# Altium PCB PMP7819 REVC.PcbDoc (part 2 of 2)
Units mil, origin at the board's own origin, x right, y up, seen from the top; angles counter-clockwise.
Board outline 2280 x 1450 mil, 4 copper layers (Top Layer, Mid-Layer 1, Mid-Layer 2, Bottom Layer), stack 62.2 mil thick; 94 components, 42 nets, 265 pads, 199 vias.
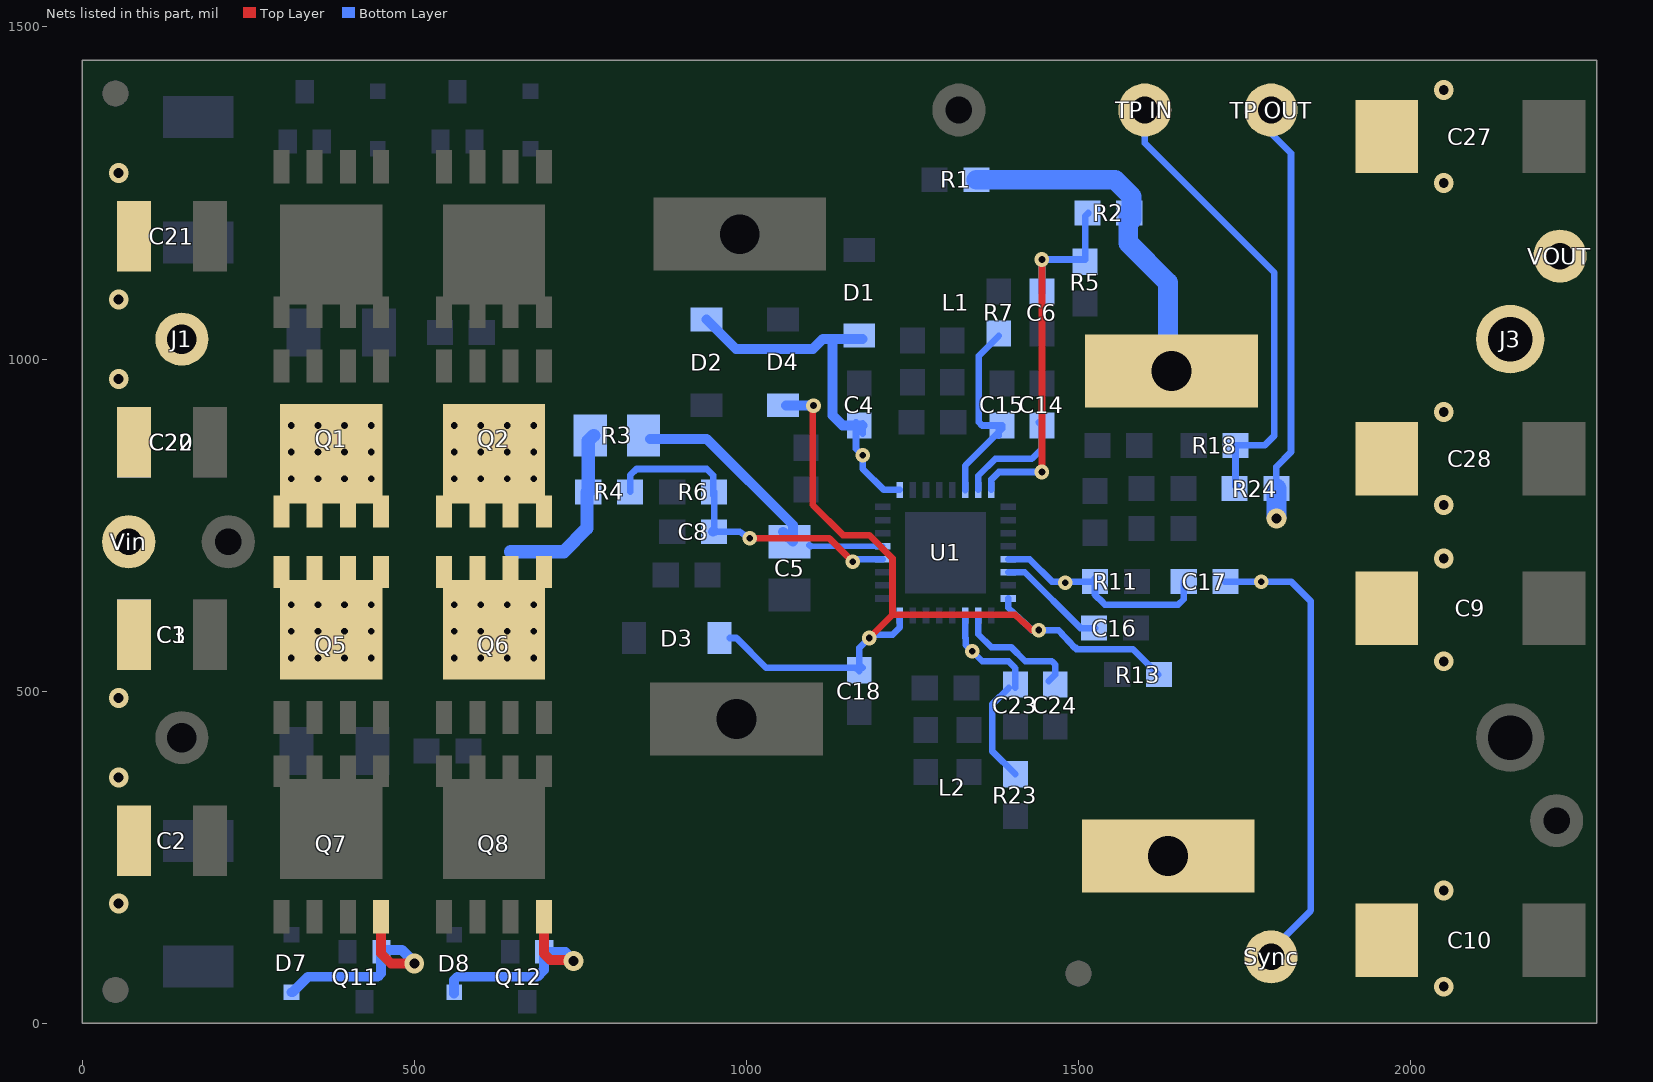
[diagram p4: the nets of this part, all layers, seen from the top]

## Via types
v1: diameter 28, hole 10, Top Layer to Bottom Layer, tented top, 96 vias
v2: diameter 30, hole 15, Top Layer to Bottom Layer, 80 vias
v3: diameter 22, hole 10, Top Layer to Bottom Layer, 23 vias

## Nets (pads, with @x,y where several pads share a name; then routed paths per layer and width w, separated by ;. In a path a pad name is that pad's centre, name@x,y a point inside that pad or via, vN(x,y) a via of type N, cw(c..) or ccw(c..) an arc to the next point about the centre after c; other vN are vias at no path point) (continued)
NetD7_1: D7.1 Q7.4 Q11.2 | length 366.5
  Top Layer w15: Q7.4@450,160 450,105 465,90 v2(500,90)
  Bottom Layer w15: D7.1@315,46.69 316.69,46.69 340,70 445,70 450,75 450,110 481.87,110 500,91.87 v2(500,90) v2@490,100
NetD8_1: D8.1 Q8.4 Q12.2 | length 344.9
  Top Layer w15: Q8.4@695,165 Q8.4@695,160.5 695,105 705,95 v2@740,95
  Bottom Layer w15: D8.1@560,45 D8.1@560,46.69 560,65 565,70 685,70 695,80 Q12.2@695,105 ; Q12.2@695.59,107.4 727.6,107.4 v2@740,95
  other v2: 740,94
NetR18_2: "TP IN.1" R18.2 R24.1 | length 692.5
  Bottom Layer w10: 1600,1340 1600,1325 1795,1130 1795,885 1780,870 R18.2@1736.5,870 ; R24.1@1740,805 1736.5,808.5 R18.2@1736.5,870 ; 1762.01,870 R18.2@1736.5,870
RAMP1: C15.1 R7.1 U1.6 | length 315.4
  Bottom Layer w10: U1.6@1329.53,802.93 1329.53,839.53 1352.67,862.67 1385,895 C15.1@1385,900 1355,900 1350,905 1350,915 ; 1350,914.18 1350,1005 R7.1@1380,1035 ; C15.1@1380,885 C15.1@1380,900
RAMP2: C23.1 R23.1 U1.19 | length 318.4
  Bottom Layer w9.84: U1.19@1329.53,613.95 1329.53,580.47 1330,580 1330,570 v3(1340,560) 1355,545 1394.77,545 1405,534.77 C23.1@1405,505
  Bottom Layer w10: C23.1@1395,505 1370,480 1370,410 R23.1@1405,375
RES: C16.1 U1.14 | length 165.3
  Bottom Layer w9.84: U1.14@1394.49,678.91 1419.01,678.91 1502.92,595 C16.1@1525,595
RT: C17.2 R11.2 U1.13 | length 358.3
  Bottom Layer w9.84: 1411.17,698.6 U1.13@1394.49,698.6 1426.4,698.6 1460,665 R11.2@1525,665
  Bottom Layer w10: R11.2@1525,670 1525,645 1536.7,633.3 ; 1535,635 1540,630 1650,630 1658.5,638.5 C17.2@1658.5,665
  other v3: 1480,663
SS1: C14.1 U1.7 | length 176
  Bottom Layer w9.84: U1.7@1349.21,802.93 1349.21,824.21 1375,850 1430,850 1445,865 C14.1@1445,900 C14.1@1440,905
SS2: C24.1 U1.18 | length 192.1
  Bottom Layer w9.84: U1.18@1349.21,613.95 1349.21,585.79 1368.61,566.4 1398.61,566.4 1420,545 1460,545 1465,540 1465,525 C24.1@1455,515
SYNC: C17.1 Sync.1 | length 706.4
  Bottom Layer w10: C17.1@1720,665 v3(1775,665) 1820,665 1850,635 1850,170 Sync.1@1780,100
UVLO: C8.1 R4.1 R6.2 U1.28 | length 518.1
  Top Layer w10: v3(1005,730) 1125,730 v3(1160,695)
  Bottom Layer w9.84: v3(1160,695) 1163.6,698.6 U1.28@1205.51,698.6
  Bottom Layer w10: R4.1@825,800 825,825 834.6,834.6 940.4,834.6 950,825 R6.2@950,795 ; C8.1@951.5,741.5 R6.2@951.5,800 ; C8.1@955,740 990,740 v3(1005,730)
  Bottom Layer w15: C8.1@950,740 C8.1@951.5,741.5
VCC1: C4.1 D1.1 D2.2 U1.1 | length 584.9
  Bottom Layer w9.84: v3(1175,855) 1175,835 1207.07,802.93 U1.1@1231.1,802.93 ; C4.1@1175,887.5 C4.1@1175,903
  Bottom Layer w10: C4.1@1165,905 1165,865 v3(1175,855)
  Bottom Layer w15: D2.2@940,1059.47 984.47,1015 1100,1015 1115,1030 D1.1@1175,1030 ; 1130,1030 1130,915 1145,900 C4.1@1175,900
VCC2: C18.1 D3.2 D4.1 R13.1 U1.16 U1.24 | length 1331.1
  Top Layer w10: v3@1100,930 1100,780.46 1145.46,735 1185,735 1220,700 1220,615 ; v3(1185,580) 1220,615 ; v3(1440,592) 1430,592 1405,615 1220,615
  Bottom Layer w9.84: C18.1@1175,535 1170,540 1170,565 1180,575 1185,575 v3(1185,580) 1190,585 1220,585 1231.1,596.1 U1.24@1231.1,613.95 ; U1.16@1394.49,639.54 1394.49,625.51 1430,592 1470,592 1495,565 1496.84,565 1496.84,563.38 1581.62,563.38 R13.1@1620,525
  Bottom Layer w10: D3.2@975,580 985,580 1030,535 1165,535 C18.1@1170,530
  Bottom Layer w15: D4.1@1060,930 v3@1100,930
  other v3: 1101,930
VCCDIS: C6.1 R2.1 R5.1 U1.8 | length 603.6
  Top Layer w10: v3(1445,830) 1445,1050 v3(1445,1150)
  Bottom Layer w9.84: U1.8@1368.9,802.93 1368.9,818.67 1380.23,830 v3(1445,830)
  Bottom Layer w10: C6.1@1445,1100 v3(1445,1150) 1510,1150 1510,1215 R2.1@1515,1220
VIN: C1.1 C2.1 C3.1 C20.1 C21.1 C22.1 J1.1 Q1.5 Q1.6 Q1.7 Q1.8 Q1.9 Q2.5 Q2.6 Q2.7 Q2.8 Q2.9 Q5.5 Q5.6 Q5.7 Q5.8 Q5.9 Q6.5 Q6.6 Q6.7 Q6.8 Q6.9 R3.2 R4.2 Vin.1 | length 279.9
  Bottom Layer w20: 645,710 725,710 760,745 760,800 R4.2@765,805 ; R4.2@762.01,800 762.01,877.01 R3.2@770,885
  other v1: 315,550 355,550 395,550 435,550 560,550 600,550 640,550 680,550 315,590 355,590 395,590 435,590 560,590 600,590 640,590 680,590 315,630 355,630 395,630 435,630 560,630 600,630 640,630 680,630 315,820 355,820 395,820 435,820 560,820 600,820 640,820 680,820 315,860 355,860 395,860 435,860 560,860 600,860 640,860 680,860 315,900 355,900 395,900 435,900 560,900 600,900 640,900 680,900
  other v2: 55,180 55,370 55,490 55,970 55,1090 55,1280
"VIN U1": C5.1 R3.1 U1.29 | length 426.3
  Bottom Layer w8: 1096.72,718.28 U1.29@1205.51,718.28
  Bottom Layer w9.84: C5.1@1095,720 1096.72,718.28
  Bottom Layer w15: R3.1@855,880 940,880 1070,750 1070,725 C5.1@1055,740
VOUT1: "TP OUT.1" C9.1 C10.1 C27.1 C28.1 J3.1 L1.2 L2.2 R1.1 R2.2 R24.2 VOUT.1 | length 1138.2
  Bottom Layer w10: 1790,1340 1820,1310 1820,860 1797.99,837.99 R24.2@1797.99,805
  Bottom Layer w30: R1.1@1346.5,1270 1555,1270 1580,1245 R2.2@1580,1210 ; R2.2@1575,1220 1575,1175 1635,1115 L1.2@1635,985 ; v2@1797.99,762.01 R24.2@1797.99,805
  other v2: 2050,55 2050,200 2050,545 2050,700 1797.99,760 2050,780 2050,920 2050,1265 2050,1405
pads on no net: FID1.1 FID2.1 FID3.1 FID4.1 FID5.1 FID6.1 Q9.0 Q10.0 Q11.0 Q12.0

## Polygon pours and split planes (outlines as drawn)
CS2_P on Top Layer "Top Layer-CS2_P" (solid, remove dead copper, pour order 83): 120,190 415,190 415,70 530,70 530,190 660,190 660,70 805,70 805,5 120,5
CS1_P on Top Layer "Top Layer-CS1_P" (solid, remove dead copper, pour order 87): 120,1260 120,1450 750,1450 750,1260 580,1260 580,1385 465,1385 465,1260
GND on Top Layer "Top Layer-GND" (solid, remove dead copper, pour order 72): 765,1450 1140,1450 1140,1310 765,1310
HO2_N on Top Layer "Top Layer-HO2_N" (solid, remove dead copper, pour order 64): 745,355 690,355 690,215 745,215
HO2_N on Top Layer "Top Layer-HO2_N" (solid, remove dead copper, pour order 79): 285,485 415,485 415,421.19 530,421.19 530,485 660,485 660,421.19 710,421.19 710,215 285,215
VIN on Top Layer "Top Layer-VIN" (solid, remove dead copper, pour order 65): 285,935 720,935 720,515 285,515
HO1_N on Top Layer " Top Layer 1-HO1_N" (solid, remove dead copper, pour order 74): 270,1235 270,1045 335,1045 335,965 465,965 465,1045 575,1045 575,965 710,965 710,1235
GND on Top Layer "Top Layer-GND" (solid, remove dead copper, pour order 78): 740,1085 1115,1085 1115,520 740,520
GND on Top Layer "Top Layer-GND" (solid, remove dead copper, pour order 59): 750,0 750,130 1125,130 1125,0
VOUT1 on Top Layer "Top Layer-VOUT1" (solid, remove dead copper, pour order 73): 1165,1450 2075,1450 2075,1210 2300,1210 2300,975 2075,975 2075,5 1165,5
GND on Top Layer "Top Layer-GND" (solid, remove dead copper, pour order 60): 1235,770 1365,770 1365,645 1235,645
GND on Top Layer "Top Layer-GND" (solid, remove dead copper, pour order 84): 245,640 245,220 115,220 115,640
HO1_N on Top Layer "Top Layer-HO1_N" (solid, remove dead copper, pour order 89): 670,1275 1115,1275 1115,1095 670,1095
GND on Top Layer "Top Layer-GND" (solid, remove dead copper, pour order 61): 2300,960 2105,960 2105,0 2300,0
GND on Top Layer "Top Layer-GND" (solid, remove dead copper, pour order 62): 2300,1450 2300,1215 2295,1220 2105,1220 2105,1450
HO2_N on Top Layer "Top Layer 1-HO2_N" (solid, remove dead copper, pour order 63): 730,150 1115,150 1115,515 855,515 855,355 730,355
VIN on Top Layer "Top Layer-VIN" (solid, remove dead copper, pour order 66): 110,1450 110,0 0,0 0,1450
GND on Top Layer "Top Layer-GND" (solid, remove dead copper, pour order 80): 115,1295 245,1295 245,625 115,625
HO1_N on Bottom Layer "Bottom Layer-HO1_N" (solid, remove dead copper, pour order 71): 1115,1225 300,1225 300,1105 1115,1105
VOUT1 on Bottom Layer "Bottom Layer-VOUT1" (solid, remove dead copper, pour order 98): 2080,1450 1510,1450 1510,0 2080,0
GND on Bottom Layer "Bottom Layer-GND" (solid, remove dead copper, pour order 55): 1560,615 1690,615 1690,415 1390,415 1390,475 1495,475 1495,500 1640,500 1640,555 1630,565 1560,565
GND on Bottom Layer "Bottom Layer 2-GND" (solid, remove dead copper, pour order 56): 1410,735 1445,735 1455,725 1695,725 1695,690 1445,690 1445,695 1430,710 1410,710
GND on Bottom Layer "Bottom Layer-GND" (solid, remove dead copper, pour order 69): 1545,1125 1465,1125 1465,1075 1410,1075 1410,1015 1360,1015 1360,925 1470,925 1470,840 1560,840 1560,925 1515,925 1515,1040 1545,1040
GND on Bottom Layer "Bottom Layer-GND" (solid, remove dead copper, pour order 94): 2300,1450 2105,1450 2105,0 2300,0
GND on Bottom Layer "Bottom Layer-GND" (solid, remove dead copper, pour order 57): 120,1215 250,1215 245,1210 245,240 120,240
CS2_P on Bottom Layer "Bottom Layer-CS2_P" (solid, remove dead copper, pour order 70): 120,90 120,0 725,0 725,90
CS1_P on Bottom Layer "Bottom Layer-CS1_P" (solid, remove dead copper, pour order 58): 715,1360 715,1430 120,1430 120,1360
VIN on Bottom Layer "Bottom Layer-VIN" (solid, remove dead copper, pour order 92): 110,0 110,1450 0,1450 0,0
GND on Bottom Layer "Bottom Layer-GND" (solid, remove dead copper, pour order 86): 780,145 1560,145 1560,0 780,0
GND on Bottom Layer "Bottom Layer-GND" (solid, remove dead copper, pour order 88): 745,1450 1405,1450 1405,1335 745,1335
VIN on Bottom Layer "Bottom Layer-VIN" (solid, remove dead copper, pour order 77): 790,920 790,515 270,515 270,920
HO2_N on Bottom Layer "Bottom Layer-No Net" (solid, remove dead copper, pour order 82): 850,515 1115,515 1115,235 290,235 290,350 850,350
VOUT1 on Mid-Layer 1 "Mid-Layer 1-VOUT1" (solid, remove dead copper, pour order 76): 2300,1450 2300,0 1505,0 1505,1450
GND on Mid-Layer 1 "Mid-Layer 1-GND" (solid, remove dead copper, pour order 90): 745,0 1490,0 1490,600 745,600
GND on Mid-Layer 1 "Mid-Layer 1-GND" (solid, remove dead copper, pour order 91): 745,1450 745,500 1495,500 1495,1450
GND on Mid-Layer 1 "Mid-Layer 1-GND" (solid, remove dead copper, pour order 96): 235,510 130,510 130,340 235,340
VIN on Mid-Layer 1 "Mid-Layer 1-VIN" (solid, remove dead copper, pour order 68): 0,1450 730,1450 730,5 0,5
VIN on Mid-Layer 2 "Mid-Layer 2-VIN" (solid, remove dead copper, pour order 85): 5,1445 105,1445 105,0 5,0
GND on Mid-Layer 2 "Mid-Layer 2-GND" (solid, remove dead copper, pour order 97): 10,0 2285,0 2285,1450 10,1450

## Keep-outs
Keep-Out Layer:
  lines w9.87: 0,0 0,1450
  lines w10: 0,0 2300,0 2300,1450 0,1450
  text ".Layer_Name" at -1288,-5172.49 h60
  text "880" at 1252.5,-5172.49 h60

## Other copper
Top Layer:
  rectangle net CS2_P: 723,21 800,65
  rectangle net VIN: 100,990 150,1070
  text ".Layer_Name" at -1288,-5172.49 h60
  text "880" at 1252.5,-5172.49 h60
Mid-Layer 1:
  rectangle net HO1_N: 295,1105 695,1215
  rectangle net HO2_N: 295,235 695,345
  rectangle net CS1_P: 115,1385 760,1435
  rectangle net CS2_P: 110,20 800,65
Mid-Layer 2:
  rectangle net VIN: 70,990 150,1070
  rectangle net HO1_N: 295,1100 455,1220
  rectangle net HO1_N: 540,1100 700,1220
  rectangle net VIN: 300,530 455,650
  rectangle net VIN: 295,800 455,920
  rectangle net VIN: 540,800 700,920
  rectangle net VIN: 540,530 700,650
  rectangle net HO2_N: 300,230 455,350
  rectangle net HO2_N: 540,230 700,350
  rectangle net CS1_P: 120,1385 760,1435
  rectangle net CS2_P: 110,20 800,65
Bottom Layer:
  rectangle net VIN: 95,990 150,1070
  text ".Layer_Name" at -1288,-5172.49 h60
  text "880" at 1252.5,-5172.49 h60

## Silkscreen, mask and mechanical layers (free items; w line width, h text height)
Top Overlay:
  text "VIN" at 45,1000 h25 r90
  text "GND" at 45,400 h25 r90
  text ".Layer_Name" at -1288,-5172.49 h60
  text "880" at 1252.5,-5172.49 h60
Bottom Overlay:
  circle w10: c1095,314 r55
  text ".Pcb_File_Name_No_Path" at 1935,315 h35 r270
  text ".CopyrightYear" at 935,300 h35
  text "TI" at 1015,300 h35
  text "C" at 1105,300 h35
  text "UL94V-0" at 1020,225 h35
  text "MADE IN U.S." at 1300,30 h35
  text ".Layer_Name" at -1288,-5172.49 h60
  text "880" at 1252.5,-5172.49 h60
Top Paste:
  text ".Layer_Name" at -1288,-5172.49 h60
  text "881" at 1252.5,-5172.49 h60
Bottom Paste:
  text ".Layer_Name" at -1288,-5172.49 h60
  text "881" at 1252.5,-5172.49 h60
Top Solder:
  text ".Layer_Name" at -1288,-5172.49 h60
  text ".Layer_Name" at -1288,-5172.49 h60
  text "880" at 1252.5,-5172.49 h60
Bottom Solder:
  text ".Layer_Name" at -1288,-5172.49 h60
  text "880" at 1252.5,-5172.49 h60
Drill Guide:
  text ".Layer_Name" at -1288,-5172.49 h60
  text "880" at 1252.5,-5172.49 h60
M1 Board Outline:
  lines w10: 0,0 0,1450 2300,1450 2300,0 0,0
M2 Board Dimensions:
  rectangle: -1740.5,-4724.5 -1365.5,-4599.5
  rectangle: -1865.5,-4599.5 -1740.5,-4474.5
  lines w7: -1865.5,-4599.5 -865.5,-4599.5 ; -1740.5,-4724.5 -1740.5,-4474.5 ; -1615.5,-4724.5 -1615.5,-4474.5 ; -1365.5,-4724.5 -1365.5,-4474.5 ; -1115.5,-4724.5 -1115.5,-4474.5 ; -1865.5,-4724.5 -1865.5,-4474.5 -865.5,-4474.5 -865.5,-4724.5 -1865.5,-4724.5
  lines w10: -1865.5,-4789.5 -1865.5,-4769.5 ; -1805.5,-4799.5 -1865.5,-4779.5 ; -1805.5,-4759.5 -1865.5,-4779.5 ; -1641.42,-4779.5 -1865.5,-4779.5 ; -1089.58,-4779.5 -865.5,-4779.5 ; -925.5,-4799.5 -865.5,-4779.5 ; -925.5,-4759.5 -865.5,-4779.5 ; -865.5,-4789.5 -865.5,-4769.5
  text "1000 (mil)" at -1631.42,-4815.49 h60
  text ".Layer_Name" at -1288,-5172.49 h60
  text "880" at 1252.5,-5172.49 h60
M3 3D STEP Top:
  text ".Layer_Name" at -1288,-5172.49 h60
  text "880" at 1252.5,-5172.49 h60
M4 3D STEP Bottom:
  text ".Layer_Name" at -1288,-5172.49 h60
  text "880" at 1252.5,-5172.49 h60
M5 Assembly Top:
  text "COMPONENTS MARKED 'DNP' SHOULD NOT BE POPULATED, AND MAY NOT BE IN BILL OF MATERIALS" at -711.5,-4632.5 h60
  text ".Layer_Name" at -1288,-5172.49 h60
  text "880" at 1252.5,-5172.49 h60
M6 Assembly Bottom:
  text "COMPONENTS MARKED 'DNP' SHOULD NOT BE POPULATED, AND MAY NOT BE IN BILL OF MATERIALS" at -711.5,-4632.5 h60
  text ".Layer_Name" at -1288,-5172.49 h60
  text "880" at 1252.5,-5172.49 h60
M9 Title Sheet:
  drawing of 63 lines, arcs and shapes, not listed
  text "1" at -1125.16,3722.5 h70
  text "2" at 1370.5,3722.5 h70
  text "3" at 3859.84,3722.5 h70
  text "4" at 6366.51,3722.5 h70
  text "5" at 8865.5,3722.5 h70
  text "6" at 11370.5,3722.5 h70
  text "A" at -2281.5,2579.5 h70
  text "B" at -2281.5,199.5 h70
  text "B" at 12518.5,199.5 h70
  text "C" at -2281.5,-2175.5 h70
  text "C" at 12518.5,-2175.5 h70
  text "A" at 12568.5,-3187.5 h70
  text "PROJECT TITLE:" at 9478.5,-4036.5 h45
  text ".PRJ_Title" at 9528.5,-4169.83 h70
  text "FILE NAME:" at 9478.5,-4337.5 h45
  text ".PCB_File_Name_No_Path" at 9528.5,-4457.5 h70
  text "D" at -2281.5,-4545.5 h70
  text "D" at 12518.5,-4545.5 h70
  text "FAB DRAWING NUMBER:" at 9478.5,-4627.5 h45
  text "551" at 9528.5,-4782.49 h70
  text ".PRJ_BasePN" at 9723.5,-4782.49 h70
  text ".PCB_MinorRev" at 10133.5,-4782.49 h70
  text "National Semiconductor and/or its licensors do not warrant the accuracy or completeness of this specification" at 4509,-4919.34 h45
  text "DESIGNED FOR:" at 9478.5,-4937.5 h45
  text "or any information contained therein. National and/or its licensors do not warrant that this design will meet" at 4464.01,-5032 h45
  text ".PRJ_Customer" at 9528.5,-5077.5 h70
  text "the specifications, will be suitable for your application or fit for any particular purpose, or will operate in" at 4464.01,-5144.67 h45
  text ".Layer_Name" at -1288,-5172.49 h60
  text "880" at 1252.5,-5172.49 h60
  text "ALTIUM DESIGNER VERSION:" at 11023.5,-5237.5 h45
  text "an implementation. National and/or its licensors do not warrant that the design is production worthy. You should" at 4464.01,-5257.33 h45
  text ".print_Scale" at 9528.5,-5339.5 h70
  text "completely validate and test your design implementation to confirm the system functionality for your application." at 4509,-5370 h45
  text ".Application_BuildNumber" at 11073.5,-5370.83 h70
  text "1" at -1125.16,-5577.5 h70
  text "2" at 1370.5,-5577.5 h70
  text "3" at 3859.84,-5577.5 h70
  text "4" at 6366.51,-5577.5 h70
  text "5" at 8865.5,-5577.5 h70
  text "6" at 11370.5,-5577.5 h70
M10 Fab Notes:
  drawing of 203 lines, arcs and shapes, not listed
  text "DESIGN INFORMATION" at 10488.02,2811 h60
  text "(REFER ALSO ARRAY/PANEL PROFILING INFORMATION)" at 10126.46,2649.29 h60
  text "BOARD SIZE" at 9440.46,2645 h60
  text "2300MIL" at 9902.78,2517.18 h60
  text "X" at 10408.46,2517.18 h60
  text "1450MIL" at 10639.78,2517.18 h60
  text "Number of Layers :" at 9843.46,2320 h60
  text "4" at 10938.27,2310 h60
  text "8" at 10940,2185 h60
  text "MIN. TRACK WIDTH:" at 9843.46,2181 h60
  text "MIL" at 11094.46,2181 h60
  text "MIN. CLEARANCE:" at 9843.46,2049 h60
  text "8" at 10939.7,2049 h60
  text "MIL" at 11094.46,2049 h60
  text "MIN. VIA PAD SIZE:" at 9843.46,1917 h60
  text "22" at 10909.71,1917 h60
  text "MIL" at 11094.46,1917 h60
  text "0.125mm (5MIL)" at 10538.46,1775.29 h60
  text "MINIMUM ANNULAR RING" at 9514.23,1771 h60
  text "EXTERNAL" at 11246.46,1771 h60
  text "PER" at 9714.23,1653 h60
  text "IPC-D-275 CLASS 2 LEVEL C" at 9934.23,1653 h60
  text "MIL, HOLES" at 11422.46,1540.71 h60
  text "+/-" at 11030,1540 h60
  text "+/-" at 11884,1540 h60
  text "REGISTRATION TOLERANCES:" at 9514.23,1535 h60
  text "METAL" at 10714,1535 h60
  text "5" at 11290.2,1535 h60
  text "3" at 12123.2,1535 h60
  text "MIL" at 12239.46,1535 h60
  text "MATERIAL:" at 9439.46,1325.54 h60
  text "FR-4 High Tg" at 10425.9,1185.21 h60
  text "FR-4" at 9900.46,1176.64 h60
  text "X" at 10272.46,1176.64 h60
  text "OTHER" at 11348.46,1176.64 h60
  text "62 MIL (1.6mm) +/-10%" at 10180.56,1013.92 h60
  text "THICKNESS:" at 9514.23,1009.64 h60
  text "X" at 10052.4,1009.64 h60
  text "OTHER" at 11465.46,1009.64 h60
  text "TOLERANCE:" at 9514.23,851.64 h60
  text "X" at 10353.53,851.64 h60
  text "ANSI IPC-6012 TYPE 3 CLASS 2" at 10540.48,851.64 h60
  text "OTHER +/-" at 10540.46,695.64 h60
  text "BOW & TWIST:" at 9514.23,538.64 h60
  text "X" at 10353.53,538.64 h60
  text "ANSI IPC-6012 TYPE 3 CLASS 2" at 10540.48,538.64 h60
  text "OTHER +/-" at 10540.46,380.13 h60
  text "COPPER THICKNESS (FINISHED):" at 9439.46,244.64 h60
  text "1.4MIL (1oz)" at 10319.46,91.92 h60
  text "2MIL (1.4oz)" at 11086.46,91.92 h60
  text "4.2MIL (3oz)" at 11813.46,91.92 h60
  text "X" at 11697,91 h60
  text "OUTER:" at 9796.46,87.64 h60
  text "1.4MIL (1oz)" at 10669.46,-65.08 h60
  text "2.8MIL (2oz)" at 11513.46,-65.08 h60
  text "INNER SIGNAL:" at 9796.46,-69.36 h60
  text "X" at 10535,-75 h60
  text "DRILLING:" at 9439.46,-208.36 h60
  text "REFERENCE:" at 9514.23,-325.36 h60
  text "X" at 10162.46,-325.36 h60
  text "AS SHOWN" at 10349.46,-325.36 h60
  text "X" at 11063.46,-325.36 h60
  text "NC_DRILL FILES" at 11200.46,-325.36 h60
  text "PTH MIN COPPER THICKNESS:" at 9514.23,-483.36 h60
  text "X" at 10864.46,-483.36 h60
  text "1MIL" at 11001.46,-483.36 h60
  text "OTHER" at 11498.46,-483.36 h60
  text "BOARD FINISH:" at 9439.46,-642.36 h60
  text "SILKSCREEN:" at 9594.68,-760.36 h60
  text "X" at 10543.46,-760.36 h60
  text "TOP" at 10669.46,-760.36 h60
  text "X" at 11053.46,-760.36 h60
  text "BOTTOM" at 11180.46,-760.36 h60
  text "SILKSCREEN COLOR:" at 9594.68,-927.36 h60
  text "X" at 10542.42,-927.36 h60
  text "WHITE" at 10669.46,-927.36 h60
  text "OTHER" at 11180.46,-927.36 h60
  text "SOLDER RESIST COLOR:" at 9594.68,-1097.36 h60
  text "X" at 10162.42,-1256.56 h60
  text "GREEN" at 10289.46,-1256.56 h60
  text "BLUE" at 10880.46,-1256.56 h60
  text "OTHER" at 11418.46,-1256.56 h60
  text "IMMERSION GOLD (ENIG)" at 10500.46,-1445.08 h60
  text "SURFACE FINISH:" at 9439.46,-1449.36 h60
  text "Pb-FREE HASL" at 11732.75,-1449.36 h60
  text "X" at 11590,-1450 h60
  text "OTHER" at 10500.46,-1606.36 h60
  text "ARRAY/PANEL:" at 9439.46,-1785.36 h60
  text "X" at 10307,-1789 h60
  text "CUT AND TRIM PER MECH LAYER 1" at 10500.46,-1789.65 h60
  text "N.C. ROUTE" at 10500.46,-1941.36 h60
  text "V. SCORE" at 11366.46,-1941.36 h60
  text "CERTIFICATION:" at 9439.46,-2078.36 h60
  text "MATERIALS AND WORKMANSHIP FOR ALL PCBS" at 10164.46,-2078.36 h60
  text "TO MEET OR EXCEED THE REQUIREMENTS OF:" at 10164.46,-2176.36 h60
  text "X" at 9790.96,-2312.87 h60
  text "ANSI IPC-A-600F CLASS ->" at 9929.96,-2312.87 h60
  text "X" at 11569.02,-2312.87 h60
  text "2" at 11687.96,-2312.86 h60
  text "1" at 11372.96,-2314.36 h60
  text "3" at 12041.96,-2314.36 h60
  text "X" at 9793.02,-2472.36 h60
  text "UL 94V-0" at 9929.96,-2472.36 h60
  text "X" at 10605.02,-2472.36 h60
  text "RoHS" at 10741.96,-2472.36 h60
  text "OTHER" at 11386.36,-2472.36 h60
  text "PER ORDER" at 11783.42,-2472.36 h60
  text "ADDITIONAL REQUIREMENTS:" at 9439.46,-2613.36 h60
  text "MICROSECTION:" at 9514.23,-2728.36 h60
  text "YES" at 10419.96,-2728.36 h60
  text "REQUIRED" at 11281.46,-2884.51 h60
  text "BARE BOARD ELEC. TEST:" at 9514.23,-2887.36 h60
  text "NONE" at 10819.96,-2887.36 h60
  text "X" at 11154.46,-2887.36 h60
  text "PER ORDER" at 11873.46,-2887.36 h60
  text "MANUFACTURER'S ID/LOGO:" at 9514.23,-3044.36 h60
  text "X" at 11840,-3045 h60
  text "RAIL" at 10979.96,-3048.65 h60
  text "METAL" at 11471.77,-3048.65 h60
  text "SILK" at 11983.46,-3048.65 h60
  text ".Layer_Name" at -1288,-5172.49 h60
  text "880" at 1252.5,-5172.49 h60
M11 Gerber Information:
  lines w7: -2157,-5244.17 4443,-5244.17 ; -2157,-5040.83 4445,-5040.83 ; -2157,-4837.5 -2157,-5447.5 1848,-5447.5 4445,-5447.5 4445,-4837.5 -2156.5,-4837.5 -2156.5,-5447.5 -581,-5447.5 ; 308,-5447.5 308,-4837.5 ; 3037,-5447.5 3037,-5244.17
  text "ALL ARTWORK VIEWED FROM TOP SIDE" at -2093.5,-4969.67 h60
  text "PROJECT NAME =" at 383,-4969.67 h60
  text ".PRJ_Title" at 1252.5,-4969.67 h60
  text "LAYER NAME =" at -2093.5,-5172.49 h60
  text "ARTWORK #    =" at 383,-5172.49 h60
  text ".prj_BasePN" at 1428.5,-5172.49 h60
  text ".pcb_minorRev" at 1791.5,-5172.49 h60
  text "NATIONAL SEMICONDUCTOR" at 3108,-5366.34 h60
  text "PLOT NAME =" at -2093.5,-5378.34 h60
  text ".plot_File_Name" at -1288,-5378.34 h60
  text "GENERATED    :" at 383,-5378.34 h60
  text ".Print_Date" at 1252.5,-5378.34 h60
  text ".Print_Time" at 1981.5,-5378.34 h60
M12 Stackup:
  lines w8: -305,2911.5 2565,2911.5 ; -305,3054.8 2565,3054.8 ; -365,2016 ccw(c-319,2016) -319,1970 2579,1970 ccw(c2579,2016) 2625,2016 2625,3174 ccw(c2579,3174) 2579,3220 -319,3220 ccw(c-319,3174) -365,3174 -365,2016
  text "Layer Stack Up Detail for: PMP7819 REVB.PcbDoc" at -305,3092.6 h61
  text "Layer" at -305,3001.3 h33
  text "Gerber" at 713.41,3001.3 h33
  text "Copper" at 1289.57,3001.3 h33
  text "Dielectric" at 1919.61,3001.3 h33
  text "Name" at -305,2935.3 h33
  text "Document" at 713.41,2935.3 h33
  text "Thickness" at 1289.57,2935.3 h33
  text "Material" at 1919.61,2935.3 h33
  text "Top Solder Mask" at -305,2842.4 h46
  text "(.GTS)" at 713.41,2842.4 h46
  text "Solder Resist" at 1919.61,2842.4 h46
  text "Top Layer" at -305,2712.19 h46
  text "(.GTL)" at 713.41,2712.19 h46
  text "4.2mil" at 1289.57,2712.19 h46
  text "FR-4" at 1919.61,2647.08 h46
  text "Mid-Layer 1" at -305,2581.98 h46
  text "(.G1)" at 713.41,2581.98 h46
  text "1.4mil" at 1289.57,2581.98 h46
  text "FR-4" at 1919.61,2516.88 h46
  text "Mid-Layer 2" at -305,2451.77 h46
  text "(.G2)" at 713.41,2451.77 h46
  text "1.4mil" at 1289.57,2451.77 h46
  text "FR-4" at 1919.61,2386.67 h46
  text "Bottom Layer" at -305,2321.56 h46
  text "(.GBL)" at 713.41,2321.56 h46
  text "4.2mil" at 1289.57,2321.56 h46
  text "Bottom Solder Mask" at -305,2191.35 h46
  text "(.GBS)" at 713.41,2191.35 h46
  text "Solder Resist" at 1919.61,2191.35 h46
  text ".Layer_Name" at -1288,-5172.49 h60
  text "880" at 1252.5,-5172.49 h60
M13 Component Bodies Top:
  text ".Layer_Name" at -1288,-5172.49 h60
  text "880" at 1252.5,-5172.49 h60
M14 Component Bodies Bottom:
  text ".Layer_Name" at -1288,-5172.49 h60
  text "880" at 1252.5,-5172.49 h60
M15 Courtyards Top:
  text ".Layer_Name" at -1288,-5172.49 h60
  text "880" at 1252.5,-5172.49 h60
M16 Courtyards Bottom:
  text ".Layer_Name" at -1288,-5172.49 h60
  text "880" at 1252.5,-5172.49 h60
Drill Drawing:
  text ".legend" at 1060,-1950 h60
  text "Drill Table" at 1045,-2130 h60
  text ".Layer_Name" at -1288,-5172.49 h60
  text "880" at 1252.5,-5172.49 h60

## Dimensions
0,0 to 0,1450 on M2 Board Dimensions
0,0 to 2300,0 on M2 Board Dimensions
